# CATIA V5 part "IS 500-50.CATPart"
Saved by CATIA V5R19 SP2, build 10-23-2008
Part number: IS 500-50
Bounding box of the stored display mesh (mm): x -22.494 to 22.494, y -22.494 to 22.494, z 0 to 185
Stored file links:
  C:\Users\Bora\Desktop\3D Katı model\IS serisi\IS 500\IS 500-50.CATPart
  C:\Program Files\Dassault Systemes\B19\intel_a\reffiles\standard\MetricThickPitch.txt
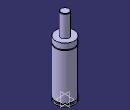
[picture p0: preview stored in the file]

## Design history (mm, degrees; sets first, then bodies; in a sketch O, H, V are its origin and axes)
Body1 (main body)
  Sketch1 on yz-plane, origin (0, 0, 0), H (0, 1, 0), V (0, 0, 1)
    point P3 (10, 184)
    point P5 (10, 184)
    point P7 (22.5, 119.5)
    point P8 (22.5, 117.5)
    point P12 (22.5, 117.5)
    point P13 (22.5, 119.5)
    line L1 (22.5, 0) -> (22.5, 4)
    line L2 (10, 184) -> (10, 133)
    arc A1 centre (9, 184) radius 1 from (10, 184) to (9, 185) ccw
    arc A2 centre (22.5, 118.5) radius 1 from (22.5, 119.5) to (22.5, 117.5) ccw
    line L3 (20, 7.5) -> (20, 4)
    line L4 (22.5, 7.5) -> (22.5, 117.5)
    line L5 (22.5, 119.5) -> (22.5, 133)
    line L6 (9, 185) -> (0, 185)
    point P15 (0, 185)
    line L7 (10, 133) -> (22.5, 133)
    line L8 (0, 0) -> (22.5, 0)
    line L9 (20, 4) -> (22.5, 4)
    line L10 (20, 7.5) -> (22.5, 7.5)
    coincidence: P15 V, P3 P5, P7 P13, P8 P12
    tangency: L6 A1
    horizontal: L7 H, L8 H, L9 H, L10 H
  Shaft1: profile Sketch1, axis Sketch1.V, angle 360
  Sketch2 on face of Shaft1 from Sketch1.L8, origin (0, 0, 0), H (1, 0, 0), V (0, -1, 0)
    point P1 (10, 0)
    distance P1 V = 10
  Hole1: placed by Sketch2, at (10, 0, 0) direction (0, 0, 1), diameter 6.647, depth 13, threaded "M8", thread diameter 8, thread depth 13, pitch 1.25
  Sketch3 on face of Shaft1 from Sketch1.L8, origin (0, 0, 0), H (1, 0, 0), V (0, -1, 0)
    point P1 (-10, 0)
    distance P1 V = 10
  Hole2: placed by Sketch3, at (-10, 0, 0) direction (0, 0, 1), diameter 6.647, depth 13, threaded "M8", thread diameter 8, thread depth 13, pitch 1.25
